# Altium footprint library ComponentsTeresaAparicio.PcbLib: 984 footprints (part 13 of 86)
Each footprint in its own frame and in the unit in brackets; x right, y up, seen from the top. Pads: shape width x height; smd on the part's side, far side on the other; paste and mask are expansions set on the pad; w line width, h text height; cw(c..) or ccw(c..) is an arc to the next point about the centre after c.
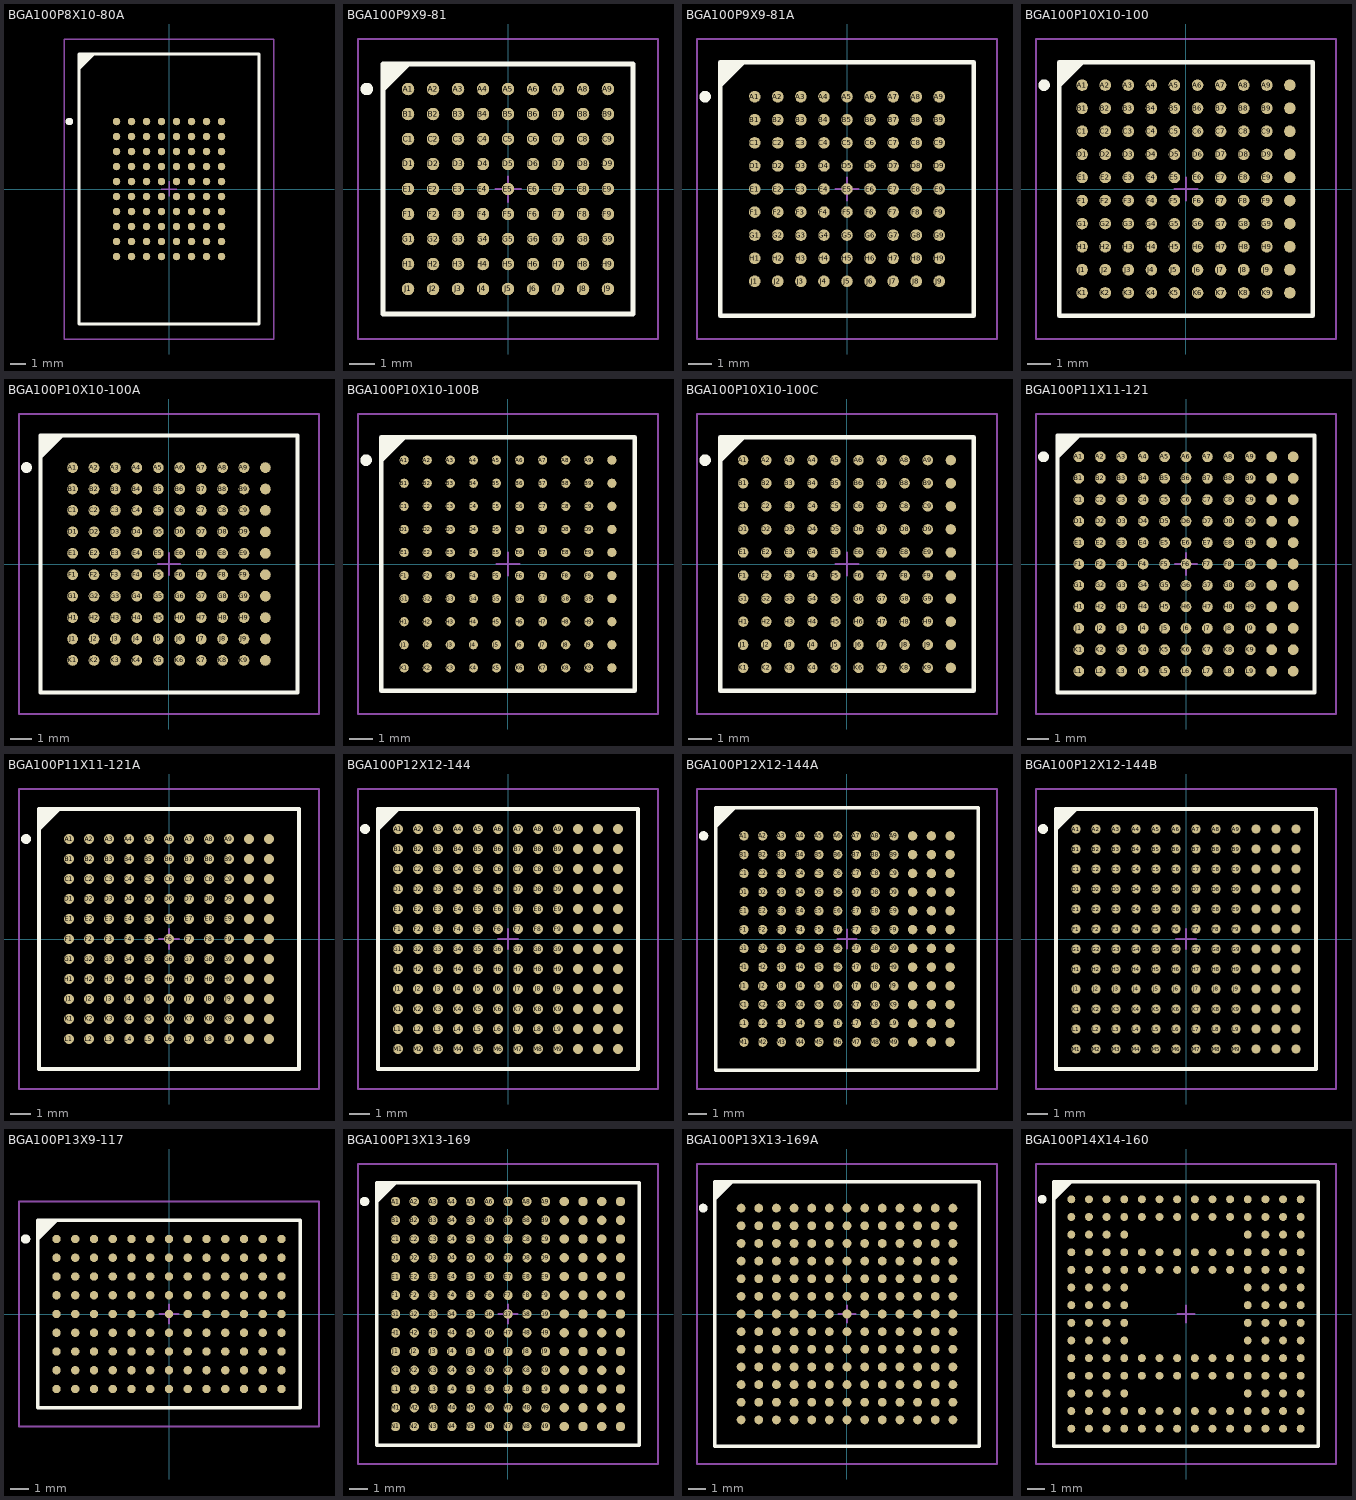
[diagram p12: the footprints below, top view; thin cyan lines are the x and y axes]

## BGA100P8X10-80A [mm] "80-Ball Fortified Ball Grid Array Rectangular 1 mm Pitch"
height 1.6
pads (80):
  round 0.5 smd: A1(-3.5,4.5) A2(-2.5,4.5) A3(-1.5,4.5) A4(-0.5,4.5) A5(0.5,4.5) A6(1.5,4.5) A7(2.5,4.5) A8(3.5,4.5) B1(-3.5,3.5) B2(-2.5,3.5) B3(-1.5,3.5) B4(-0.5,3.5) B5(0.5,3.5) B6(1.5,3.5) B7(2.5,3.5) B8(3.5,3.5) C1(-3.5,2.5) C2(-2.5,2.5) C3(-1.5,2.5) C4(-0.5,2.5) C5(0.5,2.5) C6(1.5,2.5) C7(2.5,2.5) C8(3.5,2.5) D1(-3.5,1.5) D2(-2.5,1.5) D3(-1.5,1.5) D4(-0.5,1.5) D5(0.5,1.5) D6(1.5,1.5) D7(2.5,1.5) D8(3.5,1.5) E1(-3.5,0.5) E2(-2.5,0.5) E3(-1.5,0.5) E4(-0.5,0.5) E5(0.5,0.5) E6(1.5,0.5) E7(2.5,0.5) E8(3.5,0.5) F1(-3.5,-0.5) F2(-2.5,-0.5) F3(-1.5,-0.5) F4(-0.5,-0.5) F5(0.5,-0.5) F6(1.5,-0.5) F7(2.5,-0.5) F8(3.5,-0.5) G1(-3.5,-1.5) G2(-2.5,-1.5) G3(-1.5,-1.5) G4(-0.5,-1.5) G5(0.5,-1.5) G6(1.5,-1.5) G7(2.5,-1.5) G8(3.5,-1.5) H1(-3.5,-2.5) H2(-2.5,-2.5) H3(-1.5,-2.5) H4(-0.5,-2.5) H5(0.5,-2.5) H6(1.5,-2.5) H7(2.5,-2.5) H8(3.5,-2.5) J1(-3.5,-3.5) J2(-2.5,-3.5) J3(-1.5,-3.5) J4(-0.5,-3.5) J5(0.5,-3.5) J6(1.5,-3.5) J7(2.5,-3.5) J8(3.5,-3.5) K1(-3.5,-4.5) K2(-2.5,-4.5) K3(-1.5,-4.5) K4(-0.5,-4.5) K5(0.5,-4.5) K6(1.5,-4.5) K7(2.5,-4.5) K8(3.5,-4.5)
Top Overlay:
  circle w0.25: c-6.65,4.5 r0.125
  region: -5,9 -6,8 -6,9
  lines w0.2: -6,8 -5,9 ; -6,-9 6,-9 6,9 -6,9 -6,-9
Mechanical 13:
  lines w0.1: -6,-9 6,-9 6,9 -6,9 -6,-9
Mechanical 15:
  lines w0.1: -0.5,0 0.5,0 ; 0,-0.5 0,0.5 ; -7,-10 7,-10 7,10 -7,10 -7,-10
3D body: height 1.6, standoff 0, extent -6,-9 6,9

## BGA100P9X9-81 [mm] "BGA, 81-Leads, Body 10x10mm, Pitch 1mm"
height 3.5
pads (81):
  round 0.5 smd: A1(-4,4) A2(-3,4) A3(-2,4) A4(-1,4) A5(0,4) A6(1,4) A7(2,4) A8(3,4) A9(4,4) B1(-4,3) B2(-3,3) B3(-2,3) B4(-1,3) B5(0,3) B6(1,3) B7(2,3) B8(3,3) B9(4,3) C1(-4,2) C2(-3,2) C3(-2,2) C4(-1,2) C5(0,2) C6(1,2) C7(2,2) C8(3,2) C9(4,2) D1(-4,1) D2(-3,1) D3(-2,1) D4(-1,1) D5(0,1) D6(1,1) D7(2,1) D8(3,1) D9(4,1) E1(-4,0) E2(-3,0) E3(-2,0) E4(-1,0) E5(0,0) E6(1,0) E7(2,0) E8(3,0) E9(4,0) F1(-4,-1) F2(-3,-1) F3(-2,-1) F4(-1,-1) F5(0,-1) F6(1,-1) F7(2,-1) F8(3,-1) F9(4,-1) G1(-4,-2) G2(-3,-2) G3(-2,-2) G4(-1,-2) G5(0,-2) G6(1,-2) G7(2,-2) G8(3,-2) G9(4,-2) H1(-4,-3) H2(-3,-3) H3(-2,-3) H4(-1,-3) H5(0,-3) H6(1,-3) H7(2,-3) H8(3,-3) H9(4,-3) J1(-4,-4) J2(-3,-4) J3(-2,-4) J4(-1,-4) J5(0,-4) J6(1,-4) J7(2,-4) J8(3,-4) J9(4,-4)
Top Overlay:
  circle w0.25: c-5.65,4 r0.125
  region: -4,5 -5,4 -5,5
  lines w0.2: -5,4 -4,5 ; -5,-5 -5,5 5,5 5,-5 -5,-5
Mechanical 13:
  lines w0.1: -5,-5 -5,5 5,5 5,-5 -5,-5
Mechanical 15:
  lines w0.1: -0.5,0 0.5,0 ; 0,-0.5 0,0.5 ; -6,-6 -6,6 6,6 6,-6 -6,-6
3D body: height 0, standoff 0, extent -5,-5 5,5

## BGA100P9X9-81A [mm] "BGA, 81-Leads, Body 11x11mm, Pitch 1mm"
height 3.5
pads (81):
  round 0.5 smd: A1(-4,4) A2(-3,4) A3(-2,4) A4(-1,4) A5(0,4) A6(1,4) A7(2,4) A8(3,4) A9(4,4) B1(-4,3) B2(-3,3) B3(-2,3) B4(-1,3) B5(0,3) B6(1,3) B7(2,3) B8(3,3) B9(4,3) C1(-4,2) C2(-3,2) C3(-2,2) C4(-1,2) C5(0,2) C6(1,2) C7(2,2) C8(3,2) C9(4,2) D1(-4,1) D2(-3,1) D3(-2,1) D4(-1,1) D5(0,1) D6(1,1) D7(2,1) D8(3,1) D9(4,1) E1(-4,0) E2(-3,0) E3(-2,0) E4(-1,0) E5(0,0) E6(1,0) E7(2,0) E8(3,0) E9(4,0) F1(-4,-1) F2(-3,-1) F3(-2,-1) F4(-1,-1) F5(0,-1) F6(1,-1) F7(2,-1) F8(3,-1) F9(4,-1) G1(-4,-2) G2(-3,-2) G3(-2,-2) G4(-1,-2) G5(0,-2) G6(1,-2) G7(2,-2) G8(3,-2) G9(4,-2) H1(-4,-3) H2(-3,-3) H3(-2,-3) H4(-1,-3) H5(0,-3) H6(1,-3) H7(2,-3) H8(3,-3) H9(4,-3) J1(-4,-4) J2(-3,-4) J3(-2,-4) J4(-1,-4) J5(0,-4) J6(1,-4) J7(2,-4) J8(3,-4) J9(4,-4)
Top Overlay:
  circle w0.25: c-6.15,4 r0.125
  region: -4.5,5.5 -5.5,4.5 -5.5,5.5
  lines w0.2: -5.5,4.5 -4.5,5.5 ; -5.5,-5.5 5.5,-5.5 5.5,5.5 -5.5,5.5 -5.5,-5.5
Mechanical 13:
  lines w0.1: -5.5,-5.5 5.5,-5.5 5.5,5.5 -5.5,5.5 -5.5,-5.5
Mechanical 15:
  lines w0.1: -0.5,0 0.5,0 ; 0,-0.5 0,0.5 ; -6.5,-6.5 6.5,-6.5 6.5,6.5 -6.5,6.5 -6.5,-6.5
3D body: height 0, standoff 0, extent -5.5,-5.5 5.5,5.5

## BGA100P10X10-100 [mm] "BGA, 100-Leads, Body 11x11mm, Pitch 1mm"
height 1.7
pads (100):
  round 0.5 smd: A1(-4.5,4.5) A2(-3.5,4.5) A3(-2.5,4.5) A4(-1.5,4.5) A5(-0.5,4.5) A6(0.5,4.5) A7(1.5,4.5) A8(2.5,4.5) A9(3.5,4.5) A10(4.5,4.5) B1(-4.5,3.5) B2(-3.5,3.5) B3(-2.5,3.5) B4(-1.5,3.5) B5(-0.5,3.5) B6(0.5,3.5) B7(1.5,3.5) B8(2.5,3.5) B9(3.5,3.5) B10(4.5,3.5) C1(-4.5,2.5) C2(-3.5,2.5) C3(-2.5,2.5) C4(-1.5,2.5) C5(-0.5,2.5) C6(0.5,2.5) C7(1.5,2.5) C8(2.5,2.5) C9(3.5,2.5) C10(4.5,2.5) D1(-4.5,1.5) D2(-3.5,1.5) D3(-2.5,1.5) D4(-1.5,1.5) D5(-0.5,1.5) D6(0.5,1.5) D7(1.5,1.5) D8(2.5,1.5) D9(3.5,1.5) D10(4.5,1.5) E1(-4.5,0.5) E2(-3.5,0.5) E3(-2.5,0.5) E4(-1.5,0.5) E5(-0.5,0.5) E6(0.5,0.5) E7(1.5,0.5) E8(2.5,0.5) E9(3.5,0.5) E10(4.5,0.5) F1(-4.5,-0.5) F2(-3.5,-0.5) F3(-2.5,-0.5) F4(-1.5,-0.5) F5(-0.5,-0.5) F6(0.5,-0.5) F7(1.5,-0.5) F8(2.5,-0.5) F9(3.5,-0.5) F10(4.5,-0.5) G1(-4.5,-1.5) G2(-3.5,-1.5) G3(-2.5,-1.5) G4(-1.5,-1.5) G5(-0.5,-1.5) G6(0.5,-1.5) G7(1.5,-1.5) G8(2.5,-1.5) G9(3.5,-1.5) G10(4.5,-1.5) H1(-4.5,-2.5) H2(-3.5,-2.5) H3(-2.5,-2.5) H4(-1.5,-2.5) H5(-0.5,-2.5) H6(0.5,-2.5) H7(1.5,-2.5) H8(2.5,-2.5) H9(3.5,-2.5) H10(4.5,-2.5) J1(-4.5,-3.5) J2(-3.5,-3.5) J3(-2.5,-3.5) J4(-1.5,-3.5) J5(-0.5,-3.5) J6(0.5,-3.5) J7(1.5,-3.5) J8(2.5,-3.5) J9(3.5,-3.5) J10(4.5,-3.5) K1(-4.5,-4.5) K2(-3.5,-4.5) K3(-2.5,-4.5) K4(-1.5,-4.5) K5(-0.5,-4.5) K6(0.5,-4.5) K7(1.5,-4.5) K8(2.5,-4.5) K9(3.5,-4.5) K10(4.5,-4.5)
Top Overlay:
  circle w0.25: c-6.15,4.5 r0.125
  region: -4.5,5.5 -5.5,4.5 -5.5,5.5
  lines w0.2: -5.5,4.5 -4.5,5.5 ; -5.5,-5.5 5.5,-5.5 5.5,5.5 -5.5,5.5 -5.5,-5.5
Mechanical 13:
  lines w0.1: -5.5,-5.5 5.5,-5.5 5.5,5.5 -5.5,5.5 -5.5,-5.5
Mechanical 15:
  lines w0.1: -0.5,0 0.5,0 ; 0,-0.5 0,0.5 ; -6.5,-6.5 6.5,-6.5 6.5,6.5 -6.5,6.5 -6.5,-6.5
3D body: height 0, standoff 0, extent -5.5,-5.5 5.5,5.5

## BGA100P10X10-100A [mm] "BGA, 100-Leads, Body 12x12mm, Pitch 1mm"
height 3.5
pads (100):
  round 0.5 smd: A1(-4.5,4.5) A2(-3.5,4.5) A3(-2.5,4.5) A4(-1.5,4.5) A5(-0.5,4.5) A6(0.5,4.5) A7(1.5,4.5) A8(2.5,4.5) A9(3.5,4.5) A10(4.5,4.5) B1(-4.5,3.5) B2(-3.5,3.5) B3(-2.5,3.5) B4(-1.5,3.5) B5(-0.5,3.5) B6(0.5,3.5) B7(1.5,3.5) B8(2.5,3.5) B9(3.5,3.5) B10(4.5,3.5) C1(-4.5,2.5) C2(-3.5,2.5) C3(-2.5,2.5) C4(-1.5,2.5) C5(-0.5,2.5) C6(0.5,2.5) C7(1.5,2.5) C8(2.5,2.5) C9(3.5,2.5) C10(4.5,2.5) D1(-4.5,1.5) D2(-3.5,1.5) D3(-2.5,1.5) D4(-1.5,1.5) D5(-0.5,1.5) D6(0.5,1.5) D7(1.5,1.5) D8(2.5,1.5) D9(3.5,1.5) D10(4.5,1.5) E1(-4.5,0.5) E2(-3.5,0.5) E3(-2.5,0.5) E4(-1.5,0.5) E5(-0.5,0.5) E6(0.5,0.5) E7(1.5,0.5) E8(2.5,0.5) E9(3.5,0.5) E10(4.5,0.5) F1(-4.5,-0.5) F2(-3.5,-0.5) F3(-2.5,-0.5) F4(-1.5,-0.5) F5(-0.5,-0.5) F6(0.5,-0.5) F7(1.5,-0.5) F8(2.5,-0.5) F9(3.5,-0.5) F10(4.5,-0.5) G1(-4.5,-1.5) G2(-3.5,-1.5) G3(-2.5,-1.5) G4(-1.5,-1.5) G5(-0.5,-1.5) G6(0.5,-1.5) G7(1.5,-1.5) G8(2.5,-1.5) G9(3.5,-1.5) G10(4.5,-1.5) H1(-4.5,-2.5) H2(-3.5,-2.5) H3(-2.5,-2.5) H4(-1.5,-2.5) H5(-0.5,-2.5) H6(0.5,-2.5) H7(1.5,-2.5) H8(2.5,-2.5) H9(3.5,-2.5) H10(4.5,-2.5) J1(-4.5,-3.5) J2(-3.5,-3.5) J3(-2.5,-3.5) J4(-1.5,-3.5) J5(-0.5,-3.5) J6(0.5,-3.5) J7(1.5,-3.5) J8(2.5,-3.5) J9(3.5,-3.5) J10(4.5,-3.5) K1(-4.5,-4.5) K2(-3.5,-4.5) K3(-2.5,-4.5) K4(-1.5,-4.5) K5(-0.5,-4.5) K6(0.5,-4.5) K7(1.5,-4.5) K8(2.5,-4.5) K9(3.5,-4.5) K10(4.5,-4.5)
Top Overlay:
  circle w0.25: c-6.65,4.5 r0.125
  region: -5,6 -6,5 -6,6
  lines w0.2: -6,5 -5,6 ; -6,-6 6,-6 6,6 -6,6 -6,-6
Mechanical 13:
  lines w0.1: -6,-6 6,-6 6,6 -6,6 -6,-6
Mechanical 15:
  lines w0.1: -0.5,0 0.5,0 ; 0,-0.5 0,0.5 ; -7,-7 7,-7 7,7 -7,7 -7,-7
3D body: height 0, standoff 0, extent -6,-6 6,6

## BGA100P10X10-100B [mm] "BGA, 100-Leads, Body 11x11mm, Pitch 1mm"
height 1.4
pads (100):
  round 0.4 smd: A1(-4.5,4.5) A2(-3.5,4.5) A3(-2.5,4.5) A4(-1.5,4.5) A5(-0.5,4.5) A6(0.5,4.5) A7(1.5,4.5) A8(2.5,4.5) A9(3.5,4.5) A10(4.5,4.5) B1(-4.5,3.5) B2(-3.5,3.5) B3(-2.5,3.5) B4(-1.5,3.5) B5(-0.5,3.5) B6(0.5,3.5) B7(1.5,3.5) B8(2.5,3.5) B9(3.5,3.5) B10(4.5,3.5) C1(-4.5,2.5) C2(-3.5,2.5) C3(-2.5,2.5) C4(-1.5,2.5) C5(-0.5,2.5) C6(0.5,2.5) C7(1.5,2.5) C8(2.5,2.5) C9(3.5,2.5) C10(4.5,2.5) D1(-4.5,1.5) D2(-3.5,1.5) D3(-2.5,1.5) D4(-1.5,1.5) D5(-0.5,1.5) D6(0.5,1.5) D7(1.5,1.5) D8(2.5,1.5) D9(3.5,1.5) D10(4.5,1.5) E1(-4.5,0.5) E2(-3.5,0.5) E3(-2.5,0.5) E4(-1.5,0.5) E5(-0.5,0.5) E6(0.5,0.5) E7(1.5,0.5) E8(2.5,0.5) E9(3.5,0.5) E10(4.5,0.5) F1(-4.5,-0.5) F2(-3.5,-0.5) F3(-2.5,-0.5) F4(-1.5,-0.5) F5(-0.5,-0.5) F6(0.5,-0.5) F7(1.5,-0.5) F8(2.5,-0.5) F9(3.5,-0.5) F10(4.5,-0.5) G1(-4.5,-1.5) G2(-3.5,-1.5) G3(-2.5,-1.5) G4(-1.5,-1.5) G5(-0.5,-1.5) G6(0.5,-1.5) G7(1.5,-1.5) G8(2.5,-1.5) G9(3.5,-1.5) G10(4.5,-1.5) H1(-4.5,-2.5) H2(-3.5,-2.5) H3(-2.5,-2.5) H4(-1.5,-2.5) H5(-0.5,-2.5) H6(0.5,-2.5) H7(1.5,-2.5) H8(2.5,-2.5) H9(3.5,-2.5) H10(4.5,-2.5) J1(-4.5,-3.5) J2(-3.5,-3.5) J3(-2.5,-3.5) J4(-1.5,-3.5) J5(-0.5,-3.5) J6(0.5,-3.5) J7(1.5,-3.5) J8(2.5,-3.5) J9(3.5,-3.5) J10(4.5,-3.5) K1(-4.5,-4.5) K2(-3.5,-4.5) K3(-2.5,-4.5) K4(-1.5,-4.5) K5(-0.5,-4.5) K6(0.5,-4.5) K7(1.5,-4.5) K8(2.5,-4.5) K9(3.5,-4.5) K10(4.5,-4.5)
Top Overlay:
  circle w0.25: c-6.15,4.5 r0.125
  region: -4.5,5.5 -5.5,4.5 -5.5,5.5
  lines w0.2: -5.5,4.5 -4.5,5.5 ; -5.5,-5.5 5.5,-5.5 5.5,5.5 -5.5,5.5 -5.5,-5.5
Mechanical 13:
  lines w0.1: -5.5,-5.5 5.5,-5.5 5.5,5.5 -5.5,5.5 -5.5,-5.5
Mechanical 15:
  lines w0.1: -0.5,0 0.5,0 ; 0,-0.5 0,0.5 ; -6.5,-6.5 6.5,-6.5 6.5,6.5 -6.5,6.5 -6.5,-6.5
3D body: height 0, standoff 0, extent -5.5,-5.5 5.5,5.5

## BGA100P10X10-100C [mm] "BGA, 100-Leads, Body 11x11mm, Pitch 1mm"
height 1.55
pads (100):
  round 0.45 smd: A1(-4.5,4.5) A2(-3.5,4.5) A3(-2.5,4.5) A4(-1.5,4.5) A5(-0.5,4.5) A6(0.5,4.5) A7(1.5,4.5) A8(2.5,4.5) A9(3.5,4.5) A10(4.5,4.5) B1(-4.5,3.5) B2(-3.5,3.5) B3(-2.5,3.5) B4(-1.5,3.5) B5(-0.5,3.5) B6(0.5,3.5) B7(1.5,3.5) B8(2.5,3.5) B9(3.5,3.5) B10(4.5,3.5) C1(-4.5,2.5) C2(-3.5,2.5) C3(-2.5,2.5) C4(-1.5,2.5) C5(-0.5,2.5) C6(0.5,2.5) C7(1.5,2.5) C8(2.5,2.5) C9(3.5,2.5) C10(4.5,2.5) D1(-4.5,1.5) D2(-3.5,1.5) D3(-2.5,1.5) D4(-1.5,1.5) D5(-0.5,1.5) D6(0.5,1.5) D7(1.5,1.5) D8(2.5,1.5) D9(3.5,1.5) D10(4.5,1.5) E1(-4.5,0.5) E2(-3.5,0.5) E3(-2.5,0.5) E4(-1.5,0.5) E5(-0.5,0.5) E6(0.5,0.5) E7(1.5,0.5) E8(2.5,0.5) E9(3.5,0.5) E10(4.5,0.5) F1(-4.5,-0.5) F2(-3.5,-0.5) F3(-2.5,-0.5) F4(-1.5,-0.5) F5(-0.5,-0.5) F6(0.5,-0.5) F7(1.5,-0.5) F8(2.5,-0.5) F9(3.5,-0.5) F10(4.5,-0.5) G1(-4.5,-1.5) G2(-3.5,-1.5) G3(-2.5,-1.5) G4(-1.5,-1.5) G5(-0.5,-1.5) G6(0.5,-1.5) G7(1.5,-1.5) G8(2.5,-1.5) G9(3.5,-1.5) G10(4.5,-1.5) H1(-4.5,-2.5) H2(-3.5,-2.5) H3(-2.5,-2.5) H4(-1.5,-2.5) H5(-0.5,-2.5) H6(0.5,-2.5) H7(1.5,-2.5) H8(2.5,-2.5) H9(3.5,-2.5) H10(4.5,-2.5) J1(-4.5,-3.5) J2(-3.5,-3.5) J3(-2.5,-3.5) J4(-1.5,-3.5) J5(-0.5,-3.5) J6(0.5,-3.5) J7(1.5,-3.5) J8(2.5,-3.5) J9(3.5,-3.5) J10(4.5,-3.5) K1(-4.5,-4.5) K2(-3.5,-4.5) K3(-2.5,-4.5) K4(-1.5,-4.5) K5(-0.5,-4.5) K6(0.5,-4.5) K7(1.5,-4.5) K8(2.5,-4.5) K9(3.5,-4.5) K10(4.5,-4.5)
Top Overlay:
  circle w0.25: c-6.15,4.5 r0.125
  region: -4.5,5.5 -5.5,4.5 -5.5,5.5
  lines w0.2: -5.5,4.5 -4.5,5.5 ; -5.5,-5.5 5.5,-5.5 5.5,5.5 -5.5,5.5 -5.5,-5.5
Mechanical 13:
  lines w0.1: -5.5,-5.5 5.5,-5.5 5.5,5.5 -5.5,5.5 -5.5,-5.5
Mechanical 15:
  lines w0.1: -0.5,0 0.5,0 ; 0,-0.5 0,0.5 ; -6.5,-6.5 6.5,-6.5 6.5,6.5 -6.5,6.5 -6.5,-6.5
3D body: height 0, standoff 0, extent -5.5,-5.5 5.5,5.5

## BGA100P11X11-121 [mm] "BGA, 121-Leads, Body 12x12mm, Pitch 1mm"
height 3.5
pads (121):
  round 0.5 smd: A1(-5,5) A2(-4,5) A3(-3,5) A4(-2,5) A5(-1,5) A6(0,5) A7(1,5) A8(2,5) A9(3,5) A10(4,5) A11(5,5) B1(-5,4) B2(-4,4) B3(-3,4) B4(-2,4) B5(-1,4) B6(0,4) B7(1,4) B8(2,4) B9(3,4) B10(4,4) B11(5,4) C1(-5,3) C2(-4,3) C3(-3,3) C4(-2,3) C5(-1,3) C6(0,3) C7(1,3) C8(2,3) C9(3,3) C10(4,3) C11(5,3) D1(-5,2) D2(-4,2) D3(-3,2) D4(-2,2) D5(-1,2) D6(0,2) D7(1,2) D8(2,2) D9(3,2) D10(4,2) D11(5,2) E1(-5,1) E2(-4,1) E3(-3,1) E4(-2,1) E5(-1,1) E6(0,1) E7(1,1) E8(2,1) E9(3,1) E10(4,1) E11(5,1) F1(-5,0) F2(-4,0) F3(-3,0) F4(-2,0) F5(-1,0) F6(0,0) F7(1,0) F8(2,0) F9(3,0) F10(4,0) F11(5,0) G1(-5,-1) G2(-4,-1) G3(-3,-1) G4(-2,-1) G5(-1,-1) G6(0,-1) G7(1,-1) G8(2,-1) G9(3,-1) G10(4,-1) G11(5,-1) H1(-5,-2) H2(-4,-2) H3(-3,-2) H4(-2,-2) H5(-1,-2) H6(0,-2) H7(1,-2) H8(2,-2) H9(3,-2) H10(4,-2) H11(5,-2) J1(-5,-3) J2(-4,-3) J3(-3,-3) J4(-2,-3) J5(-1,-3) J6(0,-3) J7(1,-3) J8(2,-3) J9(3,-3) J10(4,-3) J11(5,-3) K1(-5,-4) K2(-4,-4) K3(-3,-4) K4(-2,-4) K5(-1,-4) K6(0,-4) K7(1,-4) K8(2,-4) K9(3,-4) K10(4,-4) K11(5,-4) L1(-5,-5) L2(-4,-5) L3(-3,-5) L4(-2,-5) L5(-1,-5) L6(0,-5) L7(1,-5) L8(2,-5) L9(3,-5) L10(4,-5) L11(5,-5)
Top Overlay:
  circle w0.25: c-6.65,5 r0.125
  region: -5,6 -6,5 -6,6
  lines w0.2: -6,5 -5,6 ; -6,-6 6,-6 6,6 -6,6 -6,-6
Mechanical 13:
  lines w0.1: -6,-6 6,-6 6,6 -6,6 -6,-6
Mechanical 15:
  lines w0.1: -0.5,0 0.5,0 ; 0,-0.5 0,0.5 ; -7,-7 7,-7 7,7 -7,7 -7,-7
3D body: height 0, standoff 0, extent -6,-6 6,6

## BGA100P11X11-121A [mm] "BGA, 121-Leads, Body 13x13mm, Pitch 1mm"
height 3.5
pads (121):
  round 0.5 smd: A1(-5,5) A2(-4,5) A3(-3,5) A4(-2,5) A5(-1,5) A6(0,5) A7(1,5) A8(2,5) A9(3,5) A10(4,5) A11(5,5) B1(-5,4) B2(-4,4) B3(-3,4) B4(-2,4) B5(-1,4) B6(0,4) B7(1,4) B8(2,4) B9(3,4) B10(4,4) B11(5,4) C1(-5,3) C2(-4,3) C3(-3,3) C4(-2,3) C5(-1,3) C6(0,3) C7(1,3) C8(2,3) C9(3,3) C10(4,3) C11(5,3) D1(-5,2) D2(-4,2) D3(-3,2) D4(-2,2) D5(-1,2) D6(0,2) D7(1,2) D8(2,2) D9(3,2) D10(4,2) D11(5,2) E1(-5,1) E2(-4,1) E3(-3,1) E4(-2,1) E5(-1,1) E6(0,1) E7(1,1) E8(2,1) E9(3,1) E10(4,1) E11(5,1) F1(-5,0) F2(-4,0) F3(-3,0) F4(-2,0) F5(-1,0) F6(0,0) F7(1,0) F8(2,0) F9(3,0) F10(4,0) F11(5,0) G1(-5,-1) G2(-4,-1) G3(-3,-1) G4(-2,-1) G5(-1,-1) G6(0,-1) G7(1,-1) G8(2,-1) G9(3,-1) G10(4,-1) G11(5,-1) H1(-5,-2) H2(-4,-2) H3(-3,-2) H4(-2,-2) H5(-1,-2) H6(0,-2) H7(1,-2) H8(2,-2) H9(3,-2) H10(4,-2) H11(5,-2) J1(-5,-3) J2(-4,-3) J3(-3,-3) J4(-2,-3) J5(-1,-3) J6(0,-3) J7(1,-3) J8(2,-3) J9(3,-3) J10(4,-3) J11(5,-3) K1(-5,-4) K2(-4,-4) K3(-3,-4) K4(-2,-4) K5(-1,-4) K6(0,-4) K7(1,-4) K8(2,-4) K9(3,-4) K10(4,-4) K11(5,-4) L1(-5,-5) L2(-4,-5) L3(-3,-5) L4(-2,-5) L5(-1,-5) L6(0,-5) L7(1,-5) L8(2,-5) L9(3,-5) L10(4,-5) L11(5,-5)
Top Overlay:
  circle w0.25: c-7.15,5 r0.125
  region: -5.5,6.5 -6.5,5.5 -6.5,6.5
  lines w0.2: -6.5,5.5 -5.5,6.5 ; -6.5,-6.5 -6.5,6.5 6.5,6.5 6.5,-6.5 -6.5,-6.5
Mechanical 13:
  lines w0.1: -6.5,-6.5 -6.5,6.5 6.5,6.5 6.5,-6.5 -6.5,-6.5
Mechanical 15:
  lines w0.1: -0.5,0 0.5,0 ; 0,-0.5 0,0.5 ; -7.5,-7.5 -7.5,7.5 7.5,7.5 7.5,-7.5 -7.5,-7.5
3D body: height 0, standoff 0, extent -6.5,-6.5 6.5,6.5

## BGA100P12X12-144 [mm] "BGA, 144-Leads, Body 13x13mm, Pitch 1mm"
height 1.7
pads (144):
  round 0.5 smd: A1(-5.5,5.5) A2(-4.5,5.5) A3(-3.5,5.5) A4(-2.5,5.5) A5(-1.5,5.5) A6(-0.5,5.5) A7(0.5,5.5) A8(1.5,5.5) A9(2.5,5.5) A10(3.5,5.5) A11(4.5,5.5) A12(5.5,5.5) B1(-5.5,4.5) B2(-4.5,4.5) B3(-3.5,4.5) B4(-2.5,4.5) B5(-1.5,4.5) B6(-0.5,4.5) B7(0.5,4.5) B8(1.5,4.5) B9(2.5,4.5) B10(3.5,4.5) B11(4.5,4.5) B12(5.5,4.5) C1(-5.5,3.5) C2(-4.5,3.5) C3(-3.5,3.5) C4(-2.5,3.5) C5(-1.5,3.5) C6(-0.5,3.5) C7(0.5,3.5) C8(1.5,3.5) C9(2.5,3.5) C10(3.5,3.5) C11(4.5,3.5) C12(5.5,3.5) D1(-5.5,2.5) D2(-4.5,2.5) D3(-3.5,2.5) D4(-2.5,2.5) D5(-1.5,2.5) D6(-0.5,2.5) D7(0.5,2.5) D8(1.5,2.5) D9(2.5,2.5) D10(3.5,2.5) D11(4.5,2.5) D12(5.5,2.5) E1(-5.5,1.5) E2(-4.5,1.5) E3(-3.5,1.5) E4(-2.5,1.5) E5(-1.5,1.5) E6(-0.5,1.5) E7(0.5,1.5) E8(1.5,1.5) E9(2.5,1.5) E10(3.5,1.5) E11(4.5,1.5) E12(5.5,1.5) F1(-5.5,0.5) F2(-4.5,0.5) F3(-3.5,0.5) F4(-2.5,0.5) F5(-1.5,0.5) F6(-0.5,0.5) F7(0.5,0.5) F8(1.5,0.5) F9(2.5,0.5) F10(3.5,0.5) F11(4.5,0.5) F12(5.5,0.5) G1(-5.5,-0.5) G2(-4.5,-0.5) G3(-3.5,-0.5) G4(-2.5,-0.5) G5(-1.5,-0.5) G6(-0.5,-0.5) G7(0.5,-0.5) G8(1.5,-0.5) G9(2.5,-0.5) G10(3.5,-0.5) G11(4.5,-0.5) G12(5.5,-0.5) H1(-5.5,-1.5) H2(-4.5,-1.5) H3(-3.5,-1.5) H4(-2.5,-1.5) H5(-1.5,-1.5) H6(-0.5,-1.5) H7(0.5,-1.5) H8(1.5,-1.5) H9(2.5,-1.5) H10(3.5,-1.5) H11(4.5,-1.5) H12(5.5,-1.5) J1(-5.5,-2.5) J2(-4.5,-2.5) J3(-3.5,-2.5) J4(-2.5,-2.5) J5(-1.5,-2.5) J6(-0.5,-2.5) J7(0.5,-2.5) J8(1.5,-2.5) J9(2.5,-2.5) J10(3.5,-2.5) J11(4.5,-2.5) J12(5.5,-2.5) K1(-5.5,-3.5) K2(-4.5,-3.5) K3(-3.5,-3.5) K4(-2.5,-3.5) K5(-1.5,-3.5) K6(-0.5,-3.5) K7(0.5,-3.5) K8(1.5,-3.5) K9(2.5,-3.5) K10(3.5,-3.5) K11(4.5,-3.5) K12(5.5,-3.5) L1(-5.5,-4.5) L2(-4.5,-4.5) L3(-3.5,-4.5) L4(-2.5,-4.5) L5(-1.5,-4.5) L6(-0.5,-4.5) L7(0.5,-4.5) L8(1.5,-4.5) L9(2.5,-4.5) L10(3.5,-4.5) L11(4.5,-4.5) L12(5.5,-4.5) M1(-5.5,-5.5) M2(-4.5,-5.5) M3(-3.5,-5.5) M4(-2.5,-5.5) M5(-1.5,-5.5) M6(-0.5,-5.5) M7(0.5,-5.5) M8(1.5,-5.5) M9(2.5,-5.5) M10(3.5,-5.5) M11(4.5,-5.5) M12(5.5,-5.5)
Top Overlay:
  circle w0.25: c-7.15,5.5 r0.125
  region: -5.5,6.5 -6.5,5.5 -6.5,6.5
  lines w0.2: -6.5,5.5 -5.5,6.5 ; -6.5,-6.5 6.5,-6.5 6.5,6.5 -6.5,6.5 -6.5,-6.5
Mechanical 13:
  lines w0.1: -6.5,-6.5 6.5,-6.5 6.5,6.5 -6.5,6.5 -6.5,-6.5
Mechanical 15:
  lines w0.1: -0.5,0 0.5,0 ; 0,-0.5 0,0.5 ; -7.5,-7.5 7.5,-7.5 7.5,7.5 -7.5,7.5 -7.5,-7.5
3D body: height 0, standoff 0, extent -6.5,-6.5 6.5,6.5

## BGA100P12X12-144A [mm] "BGA, 144-Leads, Body 14x14mm, Pitch 1mm"
height 3.5
pads (144):
  round 0.5 smd: A1(-5.5,5.5) A2(-4.5,5.5) A3(-3.5,5.5) A4(-2.5,5.5) A5(-1.5,5.5) A6(-0.5,5.5) A7(0.5,5.5) A8(1.5,5.5) A9(2.5,5.5) A10(3.5,5.5) A11(4.5,5.5) A12(5.5,5.5) B1(-5.5,4.5) B2(-4.5,4.5) B3(-3.5,4.5) B4(-2.5,4.5) B5(-1.5,4.5) B6(-0.5,4.5) B7(0.5,4.5) B8(1.5,4.5) B9(2.5,4.5) B10(3.5,4.5) B11(4.5,4.5) B12(5.5,4.5) C1(-5.5,3.5) C2(-4.5,3.5) C3(-3.5,3.5) C4(-2.5,3.5) C5(-1.5,3.5) C6(-0.5,3.5) C7(0.5,3.5) C8(1.5,3.5) C9(2.5,3.5) C10(3.5,3.5) C11(4.5,3.5) C12(5.5,3.5) D1(-5.5,2.5) D2(-4.5,2.5) D3(-3.5,2.5) D4(-2.5,2.5) D5(-1.5,2.5) D6(-0.5,2.5) D7(0.5,2.5) D8(1.5,2.5) D9(2.5,2.5) D10(3.5,2.5) D11(4.5,2.5) D12(5.5,2.5) E1(-5.5,1.5) E2(-4.5,1.5) E3(-3.5,1.5) E4(-2.5,1.5) E5(-1.5,1.5) E6(-0.5,1.5) E7(0.5,1.5) E8(1.5,1.5) E9(2.5,1.5) E10(3.5,1.5) E11(4.5,1.5) E12(5.5,1.5) F1(-5.5,0.5) F2(-4.5,0.5) F3(-3.5,0.5) F4(-2.5,0.5) F5(-1.5,0.5) F6(-0.5,0.5) F7(0.5,0.5) F8(1.5,0.5) F9(2.5,0.5) F10(3.5,0.5) F11(4.5,0.5) F12(5.5,0.5) G1(-5.5,-0.5) G2(-4.5,-0.5) G3(-3.5,-0.5) G4(-2.5,-0.5) G5(-1.5,-0.5) G6(-0.5,-0.5) G7(0.5,-0.5) G8(1.5,-0.5) G9(2.5,-0.5) G10(3.5,-0.5) G11(4.5,-0.5) G12(5.5,-0.5) H1(-5.5,-1.5) H2(-4.5,-1.5) H3(-3.5,-1.5) H4(-2.5,-1.5) H5(-1.5,-1.5) H6(-0.5,-1.5) H7(0.5,-1.5) H8(1.5,-1.5) H9(2.5,-1.5) H10(3.5,-1.5) H11(4.5,-1.5) H12(5.5,-1.5) J1(-5.5,-2.5) J2(-4.5,-2.5) J3(-3.5,-2.5) J4(-2.5,-2.5) J5(-1.5,-2.5) J6(-0.5,-2.5) J7(0.5,-2.5) J8(1.5,-2.5) J9(2.5,-2.5) J10(3.5,-2.5) J11(4.5,-2.5) J12(5.5,-2.5) K1(-5.5,-3.5) K2(-4.5,-3.5) K3(-3.5,-3.5) K4(-2.5,-3.5) K5(-1.5,-3.5) K6(-0.5,-3.5) K7(0.5,-3.5) K8(1.5,-3.5) K9(2.5,-3.5) K10(3.5,-3.5) K11(4.5,-3.5) K12(5.5,-3.5) L1(-5.5,-4.5) L2(-4.5,-4.5) L3(-3.5,-4.5) L4(-2.5,-4.5) L5(-1.5,-4.5) L6(-0.5,-4.5) L7(0.5,-4.5) L8(1.5,-4.5) L9(2.5,-4.5) L10(3.5,-4.5) L11(4.5,-4.5) L12(5.5,-4.5) M1(-5.5,-5.5) M2(-4.5,-5.5) M3(-3.5,-5.5) M4(-2.5,-5.5) M5(-1.5,-5.5) M6(-0.5,-5.5) M7(0.5,-5.5) M8(1.5,-5.5) M9(2.5,-5.5) M10(3.5,-5.5) M11(4.5,-5.5) M12(5.5,-5.5)
Top Overlay:
  circle w0.25: c-7.65,5.5 r0.125
  region: -6,7 -7,6 -7,7
  lines w0.2: -7,6 -6,7 ; -7,-7 7,-7 7,7 -7,7 -7,-7
Mechanical 13:
  lines w0.1: -7,-7 7,-7 7,7 -7,7 -7,-7
Mechanical 15:
  lines w0.1: -0.5,0 0.5,0 ; 0,-0.5 0,0.5 ; -8,-8 8,-8 8,8 -8,8 -8,-8
3D body: height 0, standoff 0, extent -7,-7 7,7

## BGA100P12X12-144B [mm] "BGA, 144-Leads, Body 13x13mm, Pitch 1mm"
height 1.55
pads (144):
  round 0.45 smd: A1(-5.5,5.5) A2(-4.5,5.5) A3(-3.5,5.5) A4(-2.5,5.5) A5(-1.5,5.5) A6(-0.5,5.5) A7(0.5,5.5) A8(1.5,5.5) A9(2.5,5.5) A10(3.5,5.5) A11(4.5,5.5) A12(5.5,5.5) B1(-5.5,4.5) B2(-4.5,4.5) B3(-3.5,4.5) B4(-2.5,4.5) B5(-1.5,4.5) B6(-0.5,4.5) B7(0.5,4.5) B8(1.5,4.5) B9(2.5,4.5) B10(3.5,4.5) B11(4.5,4.5) B12(5.5,4.5) C1(-5.5,3.5) C2(-4.5,3.5) C3(-3.5,3.5) C4(-2.5,3.5) C5(-1.5,3.5) C6(-0.5,3.5) C7(0.5,3.5) C8(1.5,3.5) C9(2.5,3.5) C10(3.5,3.5) C11(4.5,3.5) C12(5.5,3.5) D1(-5.5,2.5) D2(-4.5,2.5) D3(-3.5,2.5) D4(-2.5,2.5) D5(-1.5,2.5) D6(-0.5,2.5) D7(0.5,2.5) D8(1.5,2.5) D9(2.5,2.5) D10(3.5,2.5) D11(4.5,2.5) D12(5.5,2.5) E1(-5.5,1.5) E2(-4.5,1.5) E3(-3.5,1.5) E4(-2.5,1.5) E5(-1.5,1.5) E6(-0.5,1.5) E7(0.5,1.5) E8(1.5,1.5) E9(2.5,1.5) E10(3.5,1.5) E11(4.5,1.5) E12(5.5,1.5) F1(-5.5,0.5) F2(-4.5,0.5) F3(-3.5,0.5) F4(-2.5,0.5) F5(-1.5,0.5) F6(-0.5,0.5) F7(0.5,0.5) F8(1.5,0.5) F9(2.5,0.5) F10(3.5,0.5) F11(4.5,0.5) F12(5.5,0.5) G1(-5.5,-0.5) G2(-4.5,-0.5) G3(-3.5,-0.5) G4(-2.5,-0.5) G5(-1.5,-0.5) G6(-0.5,-0.5) G7(0.5,-0.5) G8(1.5,-0.5) G9(2.5,-0.5) G10(3.5,-0.5) G11(4.5,-0.5) G12(5.5,-0.5) H1(-5.5,-1.5) H2(-4.5,-1.5) H3(-3.5,-1.5) H4(-2.5,-1.5) H5(-1.5,-1.5) H6(-0.5,-1.5) H7(0.5,-1.5) H8(1.5,-1.5) H9(2.5,-1.5) H10(3.5,-1.5) H11(4.5,-1.5) H12(5.5,-1.5) J1(-5.5,-2.5) J2(-4.5,-2.5) J3(-3.5,-2.5) J4(-2.5,-2.5) J5(-1.5,-2.5) J6(-0.5,-2.5) J7(0.5,-2.5) J8(1.5,-2.5) J9(2.5,-2.5) J10(3.5,-2.5) J11(4.5,-2.5) J12(5.5,-2.5) K1(-5.5,-3.5) K2(-4.5,-3.5) K3(-3.5,-3.5) K4(-2.5,-3.5) K5(-1.5,-3.5) K6(-0.5,-3.5) K7(0.5,-3.5) K8(1.5,-3.5) K9(2.5,-3.5) K10(3.5,-3.5) K11(4.5,-3.5) K12(5.5,-3.5) L1(-5.5,-4.5) L2(-4.5,-4.5) L3(-3.5,-4.5) L4(-2.5,-4.5) L5(-1.5,-4.5) L6(-0.5,-4.5) L7(0.5,-4.5) L8(1.5,-4.5) L9(2.5,-4.5) L10(3.5,-4.5) L11(4.5,-4.5) L12(5.5,-4.5) M1(-5.5,-5.5) M2(-4.5,-5.5) M3(-3.5,-5.5) M4(-2.5,-5.5) M5(-1.5,-5.5) M6(-0.5,-5.5) M7(0.5,-5.5) M8(1.5,-5.5) M9(2.5,-5.5) M10(3.5,-5.5) M11(4.5,-5.5) M12(5.5,-5.5)
Top Overlay:
  circle w0.25: c-7.15,5.5 r0.125
  region: -5.5,6.5 -6.5,5.5 -6.5,6.5
  lines w0.2: -6.5,5.5 -5.5,6.5 ; -6.5,-6.5 6.5,-6.5 6.5,6.5 -6.5,6.5 -6.5,-6.5
Mechanical 13:
  lines w0.1: -6.5,-6.5 6.5,-6.5 6.5,6.5 -6.5,6.5 -6.5,-6.5
Mechanical 15:
  lines w0.1: -0.5,0 0.5,0 ; 0,-0.5 0,0.5 ; -7.5,-7.5 7.5,-7.5 7.5,7.5 -7.5,7.5 -7.5,-7.5
3D body: height 0, standoff 0, extent -6.5,-6.5 6.5,6.5

## BGA100P13X9-117 [mm] "BGA, 117-Leads, Body 10.0x14.0mm,  Pitch 1.00mm"
height 1.7
pads (117):
  round 0.45 smd: A1(-6,4) A2(-5,4) A3(-4,4) A4(-3,4) A5(-2,4) A6(-1,4) A7(0,4) A8(1,4) A9(2,4) A10(3,4) A11(4,4) A12(5,4) A13(6,4) B1(-6,3) B2(-5,3) B3(-4,3) B4(-3,3) B5(-2,3) B6(-1,3) B7(0,3) B8(1,3) B9(2,3) B10(3,3) B11(4,3) B12(5,3) B13(6,3) C1(-6,2) C2(-5,2) C3(-4,2) C4(-3,2) C5(-2,2) C6(-1,2) C7(0,2) C8(1,2) C9(2,2) C10(3,2) C11(4,2) C12(5,2) C13(6,2) D1(-6,1) D2(-5,1) D3(-4,1) D4(-3,1) D5(-2,1) D6(-1,1) D7(0,1) D8(1,1) D9(2,1) D10(3,1) D11(4,1) D12(5,1) D13(6,1) E1(-6,0) E2(-5,0) E3(-4,0) E4(-3,0) E5(-2,0) E6(-1,0) E7(0,0) E8(1,0) E9(2,0) E10(3,0) E11(4,0) E12(5,0) E13(6,0) F1(-6,-1) F2(-5,-1) F3(-4,-1) F4(-3,-1) F5(-2,-1) F6(-1,-1) F7(0,-1) F8(1,-1) F9(2,-1) F10(3,-1) F11(4,-1) F12(5,-1) F13(6,-1) G1(-6,-2) G2(-5,-2) G3(-4,-2) G4(-3,-2) G5(-2,-2) G6(-1,-2) G7(0,-2) G8(1,-2) G9(2,-2) G10(3,-2) G11(4,-2) G12(5,-2) G13(6,-2) H1(-6,-3) H2(-5,-3) H3(-4,-3) H4(-3,-3) H5(-2,-3) H6(-1,-3) H7(0,-3) H8(1,-3) H9(2,-3) H10(3,-3) H11(4,-3) H12(5,-3) H13(6,-3) J1(-6,-4) J2(-5,-4) J3(-4,-4) J4(-3,-4) J5(-2,-4) J6(-1,-4) J7(0,-4) J8(1,-4) J9(2,-4) J10(3,-4) J11(4,-4) J12(5,-4) J13(6,-4)
Top Overlay:
  circle w0.25: c-7.65,4 r0.125
  region: -6,5 -7,4 -7,5
  lines w0.2: -7,4 -6,5 ; -7,-5 7,-5 7,5 -7,5 -7,-5
Mechanical 13:
  lines w0.1: -7,-5 7,-5 7,5 -7,5 -7,-5
Mechanical 15:
  lines w0.1: -0.5,0 0.5,0 ; 0,-0.5 0,0.5 ; -8,-6 8,-6 8,6 -8,6 -8,-6
3D body: height 1.7, standoff 0.31, extent -7,-5 7,5

## BGA100P13X13-169 [mm] "BGA, 169-Leads, Body 14x14mm, Pitch 1mm"
height 3.5
pads (169):
  round 0.5 smd: A1(-6,6) A2(-5,6) A3(-4,6) A4(-3,6) A5(-2,6) A6(-1,6) A7(0,6) A8(1,6) A9(2,6) A10(3,6) A11(4,6) A12(5,6) A13(6,6) B1(-6,5) B2(-5,5) B3(-4,5) B4(-3,5) B5(-2,5) B6(-1,5) B7(0,5) B8(1,5) B9(2,5) B10(3,5) B11(4,5) B12(5,5) B13(6,5) C1(-6,4) C2(-5,4) C3(-4,4) C4(-3,4) C5(-2,4) C6(-1,4) C7(0,4) C8(1,4) C9(2,4) C10(3,4) C11(4,4) C12(5,4) C13(6,4) D1(-6,3) D2(-5,3) D3(-4,3) D4(-3,3) D5(-2,3) D6(-1,3) D7(0,3) D8(1,3) D9(2,3) D10(3,3) D11(4,3) D12(5,3) D13(6,3) E1(-6,2) E2(-5,2) E3(-4,2) E4(-3,2) E5(-2,2) E6(-1,2) E7(0,2) E8(1,2) E9(2,2) E10(3,2) E11(4,2) E12(5,2) E13(6,2) F1(-6,1) F2(-5,1) F3(-4,1) F4(-3,1) F5(-2,1) F6(-1,1) F7(0,1) F8(1,1) F9(2,1) F10(3,1) F11(4,1) F12(5,1) F13(6,1) G1(-6,0) G2(-5,0) G3(-4,0) G4(-3,0) G5(-2,0) G6(-1,0) G7(0,0) G8(1,0) G9(2,0) G10(3,0) G11(4,0) G12(5,0) G13(6,0) H1(-6,-1) H2(-5,-1) H3(-4,-1) H4(-3,-1) H5(-2,-1) H6(-1,-1) H7(0,-1) H8(1,-1) H9(2,-1) H10(3,-1) H11(4,-1) H12(5,-1) H13(6,-1) J1(-6,-2) J2(-5,-2) J3(-4,-2) J4(-3,-2) J5(-2,-2) J6(-1,-2) J7(0,-2) J8(1,-2) J9(2,-2) J10(3,-2) J11(4,-2) J12(5,-2) J13(6,-2) K1(-6,-3) K2(-5,-3) K3(-4,-3) K4(-3,-3) K5(-2,-3) K6(-1,-3) K7(0,-3) K8(1,-3) K9(2,-3) K10(3,-3) K11(4,-3) K12(5,-3) K13(6,-3) L1(-6,-4) L2(-5,-4) L3(-4,-4) L4(-3,-4) L5(-2,-4) L6(-1,-4) L7(0,-4) L8(1,-4) L9(2,-4) L10(3,-4) L11(4,-4) L12(5,-4) L13(6,-4) M1(-6,-5) M2(-5,-5) M3(-4,-5) M4(-3,-5) M5(-2,-5) M6(-1,-5) M7(0,-5) M8(1,-5) M9(2,-5) M10(3,-5) M11(4,-5) M12(5,-5) M13(6,-5) N1(-6,-6) N2(-5,-6) N3(-4,-6) N4(-3,-6) N5(-2,-6) N6(-1,-6) N7(0,-6) N8(1,-6) N9(2,-6) N10(3,-6) N11(4,-6) N12(5,-6) N13(6,-6)
Top Overlay:
  circle w0.25: c-7.65,6 r0.125
  region: -6,7 -7,6 -7,7
  lines w0.2: -7,6 -6,7 ; -7,-7 7,-7 7,7 -7,7 -7,-7
Mechanical 13:
  lines w0.1: -7,-7 7,-7 7,7 -7,7 -7,-7
Mechanical 15:
  lines w0.1: -0.5,0 0.5,0 ; 0,-0.5 0,0.5 ; -8,-8 8,-8 8,8 -8,8 -8,-8
3D body: height 0, standoff 0, extent -7,-7 7,7

## BGA100P13X13-169A [mm] "BGA, 169-Leads, Body 15x15mm, Pitch 1mm"
height 3.5
pads (169):
  round 0.5 smd: A1(-6,6) A2(-5,6) A3(-4,6) A4(-3,6) A5(-2,6) A6(-1,6) A7(0,6) A8(1,6) A9(2,6) A10(3,6) A11(4,6) A12(5,6) A13(6,6) B1(-6,5) B2(-5,5) B3(-4,5) B4(-3,5) B5(-2,5) B6(-1,5) B7(0,5) B8(1,5) B9(2,5) B10(3,5) B11(4,5) B12(5,5) B13(6,5) C1(-6,4) C2(-5,4) C3(-4,4) C4(-3,4) C5(-2,4) C6(-1,4) C7(0,4) C8(1,4) C9(2,4) C10(3,4) C11(4,4) C12(5,4) C13(6,4) D1(-6,3) D2(-5,3) D3(-4,3) D4(-3,3) D5(-2,3) D6(-1,3) D7(0,3) D8(1,3) D9(2,3) D10(3,3) D11(4,3) D12(5,3) D13(6,3) E1(-6,2) E2(-5,2) E3(-4,2) E4(-3,2) E5(-2,2) E6(-1,2) E7(0,2) E8(1,2) E9(2,2) E10(3,2) E11(4,2) E12(5,2) E13(6,2) F1(-6,1) F2(-5,1) F3(-4,1) F4(-3,1) F5(-2,1) F6(-1,1) F7(0,1) F8(1,1) F9(2,1) F10(3,1) F11(4,1) F12(5,1) F13(6,1) G1(-6,0) G2(-5,0) G3(-4,0) G4(-3,0) G5(-2,0) G6(-1,0) G7(0,0) G8(1,0) G9(2,0) G10(3,0) G11(4,0) G12(5,0) G13(6,0) H1(-6,-1) H2(-5,-1) H3(-4,-1) H4(-3,-1) H5(-2,-1) H6(-1,-1) H7(0,-1) H8(1,-1) H9(2,-1) H10(3,-1) H11(4,-1) H12(5,-1) H13(6,-1) J1(-6,-2) J2(-5,-2) J3(-4,-2) J4(-3,-2) J5(-2,-2) J6(-1,-2) J7(0,-2) J8(1,-2) J9(2,-2) J10(3,-2) J11(4,-2) J12(5,-2) J13(6,-2) K1(-6,-3) K2(-5,-3) K3(-4,-3) K4(-3,-3) K5(-2,-3) K6(-1,-3) K7(0,-3) K8(1,-3) K9(2,-3) K10(3,-3) K11(4,-3) K12(5,-3) K13(6,-3) L1(-6,-4) L2(-5,-4) L3(-4,-4) L4(-3,-4) L5(-2,-4) L6(-1,-4) L7(0,-4) L8(1,-4) L9(2,-4) L10(3,-4) L11(4,-4) L12(5,-4) L13(6,-4) M1(-6,-5) M2(-5,-5) M3(-4,-5) M4(-3,-5) M5(-2,-5) M6(-1,-5) M7(0,-5) M8(1,-5) M9(2,-5) M10(3,-5) M11(4,-5) M12(5,-5) M13(6,-5) N1(-6,-6) N2(-5,-6) N3(-4,-6) N4(-3,-6) N5(-2,-6) N6(-1,-6) N7(0,-6) N8(1,-6) N9(2,-6) N10(3,-6) N11(4,-6) N12(5,-6) N13(6,-6)
Top Overlay:
  circle w0.25: c-8.15,6 r0.125
  region: -6.5,7.5 -7.5,6.5 -7.5,7.5
  lines w0.2: -7.5,6.5 -6.5,7.5 ; -7.5,-7.5 7.5,-7.5 7.5,7.5 -7.5,7.5 -7.5,-7.5
Mechanical 13:
  lines w0.1: -7.5,-7.5 7.5,-7.5 7.5,7.5 -7.5,7.5 -7.5,-7.5
Mechanical 15:
  lines w0.1: -0.5,0 0.5,0 ; 0,-0.5 0,0.5 ; -8.5,-8.5 8.5,-8.5 8.5,8.5 -8.5,8.5 -8.5,-8.5
3D body: height 0, standoff 0, extent -7.5,-7.5 7.5,7.5

## BGA100P14X14-160 [mm] "BGA, 160-Leads, Body 15x15mm, Pitch 1mm"
height 1.75
pads (160):
  round 0.45 smd: A1(-6.5,6.5) A2(-5.5,6.5) A3(-4.5,6.5) A4(-3.5,6.5) A5(-2.5,6.5) A6(-1.5,6.5) A7(-0.5,6.5) A8(0.5,6.5) A9(1.5,6.5) A10(2.5,6.5) A11(3.5,6.5) A12(4.5,6.5) A13(5.5,6.5) A14(6.5,6.5) B1(-6.5,5.5) B2(-5.5,5.5) B3(-4.5,5.5) B4(-3.5,5.5) B5(-2.5,5.5) B6(-1.5,5.5) B7(-0.5,5.5) B8(0.5,5.5) B9(1.5,5.5) B10(2.5,5.5) B11(3.5,5.5) B12(4.5,5.5) B13(5.5,5.5) B14(6.5,5.5) C1(-6.5,4.5) C2(-5.5,4.5) C3(-4.5,4.5) C4(-3.5,4.5) C11(3.5,4.5) C12(4.5,4.5) C13(5.5,4.5) C14(6.5,4.5) D1(-6.5,3.5) D2(-5.5,3.5) D3(-4.5,3.5) D4(-3.5,3.5) D5(-2.5,3.5) D6(-1.5,3.5) D7(-0.5,3.5) D8(0.5,3.5) D9(1.5,3.5) D10(2.5,3.5) D11(3.5,3.5) D12(4.5,3.5) D13(5.5,3.5) D14(6.5,3.5) E1(-6.5,2.5) E2(-5.5,2.5) E3(-4.5,2.5) E4(-3.5,2.5) E5(-2.5,2.5) E6(-1.5,2.5) E7(-0.5,2.5) E8(0.5,2.5) E9(1.5,2.5) E10(2.5,2.5) E11(3.5,2.5) E12(4.5,2.5) E13(5.5,2.5) E14(6.5,2.5) F1(-6.5,1.5) F2(-5.5,1.5) F3(-4.5,1.5) F4(-3.5,1.5) F11(3.5,1.5) F12(4.5,1.5) F13(5.5,1.5) F14(6.5,1.5) G1(-6.5,0.5) G2(-5.5,0.5) G3(-4.5,0.5) G4(-3.5,0.5) G11(3.5,0.5) G12(4.5,0.5) G13(5.5,0.5) G14(6.5,0.5) H1(-6.5,-0.5) H2(-5.5,-0.5) H3(-4.5,-0.5) H4(-3.5,-0.5) H11(3.5,-0.5) H12(4.5,-0.5) H13(5.5,-0.5) H14(6.5,-0.5) J1(-6.5,-1.5) J2(-5.5,-1.5) J3(-4.5,-1.5) J4(-3.5,-1.5) J11(3.5,-1.5) J12(4.5,-1.5) J13(5.5,-1.5) J14(6.5,-1.5) K1(-6.5,-2.5) K2(-5.5,-2.5) K3(-4.5,-2.5) K4(-3.5,-2.5) K5(-2.5,-2.5) K6(-1.5,-2.5) K7(-0.5,-2.5) K8(0.5,-2.5) K9(1.5,-2.5) K10(2.5,-2.5) K11(3.5,-2.5) K12(4.5,-2.5) K13(5.5,-2.5) K14(6.5,-2.5) L1(-6.5,-3.5) L2(-5.5,-3.5) L3(-4.5,-3.5) L4(-3.5,-3.5) L5(-2.5,-3.5) L6(-1.5,-3.5) L7(-0.5,-3.5) L8(0.5,-3.5) L9(1.5,-3.5) L10(2.5,-3.5) L11(3.5,-3.5) L12(4.5,-3.5) L13(5.5,-3.5) L14(6.5,-3.5) M1(-6.5,-4.5) M2(-5.5,-4.5) M3(-4.5,-4.5) M4(-3.5,-4.5) M11(3.5,-4.5) M12(4.5,-4.5) M13(5.5,-4.5) M14(6.5,-4.5) N1(-6.5,-5.5) N2(-5.5,-5.5) N3(-4.5,-5.5) N4(-3.5,-5.5) N5(-2.5,-5.5) N6(-1.5,-5.5) N7(-0.5,-5.5) N8(0.5,-5.5) N9(1.5,-5.5) N10(2.5,-5.5) N11(3.5,-5.5) N12(4.5,-5.5) N13(5.5,-5.5) N14(6.5,-5.5) P1(-6.5,-6.5) P2(-5.5,-6.5) P3(-4.5,-6.5) P4(-3.5,-6.5) P5(-2.5,-6.5) P6(-1.5,-6.5) P7(-0.5,-6.5) P8(0.5,-6.5) P9(1.5,-6.5) P10(2.5,-6.5) P11(3.5,-6.5) P12(4.5,-6.5) P13(5.5,-6.5) P14(6.5,-6.5)
Top Overlay:
  circle w0.25: c-8.15,6.5 r0.125
  region: -6.5,7.5 -7.5,6.5 -7.5,7.5
  lines w0.2: -7.5,6.5 -6.5,7.5 ; -7.5,-7.5 7.5,-7.5 7.5,7.5 -7.5,7.5 -7.5,-7.5
Mechanical 13:
  lines w0.1: -7.5,-7.5 7.5,-7.5 7.5,7.5 -7.5,7.5 -7.5,-7.5
Mechanical 15:
  lines w0.1: -0.5,0 0.5,0 ; 0,-0.5 0,0.5 ; -8.5,-8.5 8.5,-8.5 8.5,8.5 -8.5,8.5 -8.5,-8.5
3D body: height 0, standoff 0, extent -7.5,-7.5 7.5,7.5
